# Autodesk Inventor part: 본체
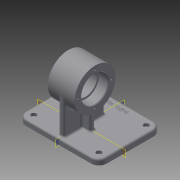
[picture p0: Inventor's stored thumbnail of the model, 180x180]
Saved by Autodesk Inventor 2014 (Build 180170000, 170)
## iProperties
Created: 2019-09
Part Number: 본체
Material: Generic
Document SubType Name: Modeling
Designer: kh
Density: 1 g/cm^3
Appearance: Default
Author: kh
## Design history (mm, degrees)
sketch "Sketch1"
  geometry: L1 (0, 0)-(126, 0); L2 (126, 0)-(126, 98); L3 (126, 98)-(0, 98); L4 (0, 98)-(0, 0)
  constraints: 8 end point, 2 parallel, 1 horizontal, 1 perpendicular
  dimensions: "d0" = 126 distance of L3.end L2.end; "d1" = 98 distance of L2.end L1.end
extrude "Extrusion1" new body sketch "Sketch1" distance "d2" = 9; taper "d3" = 0 deg
workplane "Work Plane1"
sketch "Sketch2"
  geometry: L1 (126, 9)-(0, 9) reference; L2 (42, 68)-(84, 68); L3 (84, 68)-(84, 100); L4 (84, 100)-(42, 100); L5 (42, 100)-(42, 68); L6 (42, 89)-(57, 89); L7 (57, 89)-(57, 86); L8 (57, 86)-(69, 86); L9 (69, 86)-(69, 89); L10 (69, 89)-(84, 89); L11 (0, 0)-(0, 9) reference; 1 further point
  constraints: 18 end point, 4 parallel, 4 perpendicular, 2 point on line, 1 horizontal, 1 midpoint
  dimensions: "d5" = 64 diameter of L4 L2; "d6" = 42 distance between parallel lines of L3 L5; "d7" = 36 diameter of L8 L2; "d8" = 42 diameter of L10 L2; "d9" = 42 diameter of L6 L2; "d10" = 15 distance between parallel lines of L7 L5; "d11" = 15 distance between parallel lines of L3 L9; "d13" = 59 distance between parallel lines of L2 L1; "d14" = 63 distance from line of L11 point (63, 100)
revolve "Revolution1" sketch "Sketch2" stored, may be unused: angle "d15" = 90 deg
sketch "Sketch3"
  geometry: L1 (46, 32)-(80, 32); L2 (80, 32)-(80, 40); L3 (80, 40)-(46, 40); L4 (46, 40)-(46, 32); L5 (46, 32)-(80, 40); L6 (80, 32)-(46, 40); L7 (0, 98)-(0, 0) reference; L8 (126, 98)-(0, 98) reference; 1 further point
  constraints: 12 end point, 2 midpoint, 2 parallel, 1 horizontal, 1 perpendicular
  dimensions: "d16" = 63 distance from line of point (63, 36) L7; "d17" = 8 distance between parallel lines of L1 L3; "d18" = 34 distance between parallel lines of L2 L4; "d19" = 62 distance from line of L8 point (63, 36)
extrude "Extrusion2" join sketch "Sketch3" stored distance "d20" = 0; taper "d21" = 0 deg
workplane "Work Plane2"
sketch "Sketch4"
  geometry: L1 (68, 68)-(8.954, 68); L2 (68, 4)-(8.954, 4); A1 r 32 centre (68, 36) between (68, 68) and (68, 4) reference; 1 further point
  constraints: 4 end point, 2 point on circle, 2 tangent, 1 horizontal, 1 parallel
feature "Rib1" sketch "Sketch4" dims "d23" = 1, "d24" = 8, "d25" = 0, "d26" = 0, "d27" = 1, "d28" = 1
mirror "Mirror1"
sketch "Sketch5"
  geometry: L1 (0, 0)-(26, 0); C1 r 32 at (0, 0) reference; 2 further points
  constraints: 2 end point, 1 coincident, 1 horizontal
  dimensions: "d29" = 26 distance of L1.start point (26, 0)
hole "Hole1" sketch "Sketch5" at (26, 0) diameter "d30" = 3.242; stored, may be unused: countersink angle "d34" = 90 deg, drill point angle "d36" = 118 deg; dims "d31" = 8, "d32" = 4, "d33" = 2, "d35" = 10
pattern_circular "Circular Pattern1" dims angle "d38" = 360 deg
mirror "Mirror2"
fillet "Fillet1" dims "d40" = 3
fillet "Fillet3" dims "d42" = 12
fillet "Fillet2" dims "d41" = 3
hole "Hole2" diameter "d45" = 4.5; stored, may be unused: countersink angle "d49" = 90 deg, drill point angle "d51" = 118 deg; dims "d43" = 10, "d44" = 10, "d46" = 8, "d47" = 8, "d48" = 4.4, "d50" = 10
pattern_linear "Rectangular Pattern1" dims "d54" = 74, "d57" = 102
fillet "Fillet4" dims "d58" = 0.3
sketch "Sketch6"
  geometry: L1 (49.482, 92.439)-(76.518, 92.439); L2 (76.518, 92.439)-(76.518, 83.561); L3 (76.518, 83.561)-(49.482, 83.561); L4 (49.482, 83.561)-(49.482, 92.439); L5 (49.482, 92.439)-(76.518, 83.561); L6 (76.518, 92.439)-(49.482, 83.561); L7 (114, 98)-(12, 98) reference; L8 (126, 12)-(126, 86) reference; 2 further points
  constraints: 4 end point, 1 midpoint, 2 other
  dimensions: "d59" = 10 distance from line of point (63, 88) L7; "d60" = 63 distance from line of L8 point (63, 88)
emboss "Emboss1" sketch "Sketch6" dims "d0" = 126, "d1" = 98, "d61" = 0.5, "d62" = 0
chamfer "Chamfer1" distance "d63" = 1; stored, may be unused: second distance "d64" = 2, angle "d65" = 45 deg
body "Solid1"
other parameters: "d4" = -36, "d22" = -63
